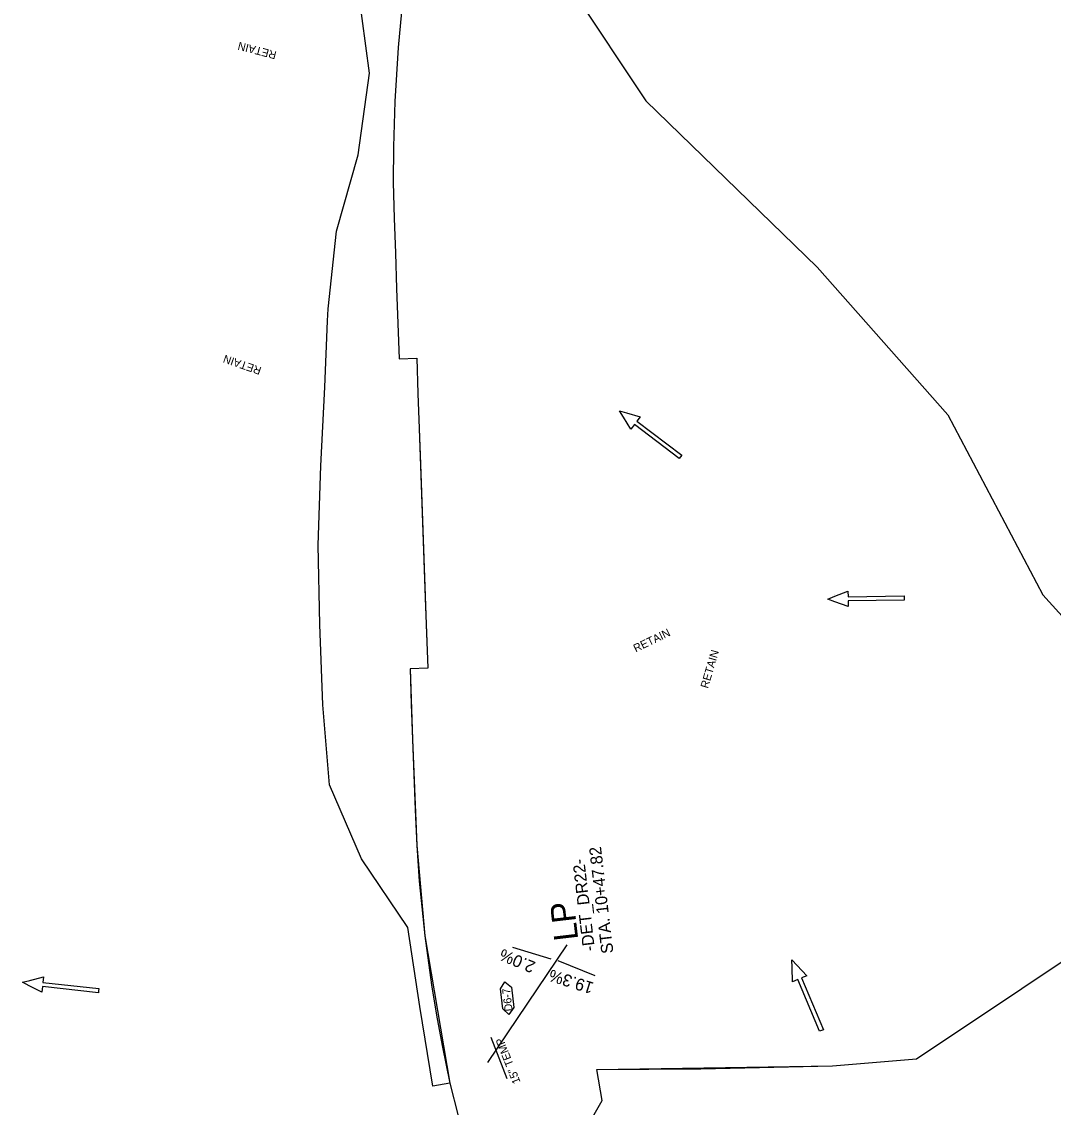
# Model space of a CAD drawing. Extents: x 465700 to 483515, y 488970 to 507540.
# Drawn here: x 474370 to 475014, y 503745 to 504423 of the extents above; entities that cross this region are included whole.
import ezdxf

# ---------------------------------------------------------------- set-up
doc = ezdxf.new("R2010")
doc.units = 0
for name, color, linetype in [('Default', 7, 'Continuous'), ('Exist Plan Preparation Drainage Flow Arrows', 7, 'Continuous'), ('Exist Plan Preparation Watershed Blue', 7, 'Continuous'), ('Prop Drainage Structure Box Number Symbol CELL', 7, 'Continuous'), ('Prop Drainage Structure Pipe Collar Label', 7, 'Continuous'), ('Prop Drainage Structure Pipe Side Drain 15in', 7, 'Continuous'), ('Prop Drainage Structure Pipe Side Drain 15in Label', 7, 'Continuous'), ('Prop Plan Preparation Sag', 7, 'Continuous'), ('Prop Plan Preparation Sag Label', 7, 'Continuous'), ('Scratch_Level_4', 7, 'Continuous')]:
    doc.layers.add(name, color=color, linetype=linetype)

# ---------------------------------------------------------------- blocks, each defined once
blk = doc.blocks.new('Existing ground flow arrow')
at = {"layer": 'Default'}
blk.add_line((2.5, -4.33), (2.5, -4.33), dxfattribs=at)
blk.add_lwpolyline([(-1.29, -47.2), (-1.28, -12.53), (-4.77, -12.53), (-1.65, -4.33), (0, 0), (1.65, -4.33), (4.78, -12.53), (1.28, -12.52), (1.29, -47.19), (0, -47.2)], close=True, dxfattribs=at)

msp = doc.modelspace()

# ---------------------------------------------------------------- linework, layer by layer
at = {"layer": 'Exist Plan Preparation Watershed Blue'}
for points in [[(474607.44, 504429.48), (474605.35, 504407.31), (474603.28, 504373.45), (474602.39, 504345.32), (474602.36, 504323.05), (474602.88, 504300.79), (474603.66, 504278.8), (474604.43, 504256.82), (474605.21, 504234.83), (474605.99, 504212.84), (474616.98, 504213.23), (474617.76, 504191.25), (474618.53, 504169.26), (474622.27, 504063.56), (474623.82, 504019.58), (474612.83, 504019.19), (474614.39, 503975.22), (474616.99, 503909.02), (474621.99, 503852.61), (474637.56, 503760.43), (474653.18, 503699.27)], [(475043.75, 503145.56), (474975.08, 503218.25), (474906.45, 503290.98), (474841.06, 503366.61), (474822.12, 503390.62), (474781.05, 503446.58), (474765.36, 503472.89), (474733.7, 503528.17), (474717.65, 503560.73), (474707.52, 503583.69), (474695.73, 503610.42), (474686.31, 503634.82), (474679.54, 503653.13), (474672.31, 503674.23), (474692.89, 503679.94), (474732.67, 503749.62), (474729.4, 503768.98), (474794.46, 503769.47), (474876.64, 503771.38), (474928.93, 503775.76), (475126.97, 503907.83)], [(474692.89, 503679.94), (474732.67, 503749.62), (474729.4, 503768.98), (474876.64, 503771.38), (474928.93, 503775.76), (475126.97, 503907.83)]]:
    msp.add_lwpolyline(points, dxfattribs=at)
at = {"layer": 'Prop Drainage Structure Box Number Symbol CELL'}
msp.add_lwpolyline([(474670.8, 503806.93), (474669.36, 503819.45), (474672.1, 503823.9), (474676.11, 503820.38), (474677.55, 503807.86), (474674.45, 503803.48), (474670.8, 503806.93)], dxfattribs=at)
at = {"layer": 'Prop Drainage Structure Pipe Side Drain 15in'}
msp.add_line((474673.45, 503763.18), (474663.56, 503788.99), dxfattribs=at)
at = {"layer": 'Prop Plan Preparation Sag'}
msp.add_line((474661.47, 503773.47), (474710.85, 503846.85), dxfattribs=at)
at = {"layer": 'Prop Plan Preparation Sag Label'}
for p, q in [((474700.83, 503837.92), (474676.93, 503845.25)), ((474705.03, 503837.08), (474728.25, 503827.81))]:
    msp.add_line(p, q, dxfattribs=at)
at = {"layer": 'Scratch_Level_4'}
msp.add_lwpolyline([(475270.85, 503809.14), (475219.84, 504084.06), (475137.95, 504274.18), (475078.19, 504412.9), (474954.65, 504479.02), (474778.74, 504535.52), (474670.15, 504603.36), (474666.14, 504603.36), (474675.38, 504549.78), (474701.44, 504496.46), (474714.87, 504441.96), (474760.12, 504373.88), (474867.06, 504270.09), (474948.55, 504177.85), (475007.9, 504065.5), (475074.01, 503992.37), (475126.97, 503907.83)], close=True, dxfattribs=at)
msp.add_lwpolyline([(474607.44, 504429.48), (474605.35, 504407.31), (474603.28, 504373.45), (474602.39, 504345.32), (474602.36, 504323.05), (474602.88, 504300.78), (474603.66, 504278.8), (474604.43, 504256.82), (474605.21, 504234.83), (474605.99, 504212.84), (474616.98, 504213.23), (474617.76, 504191.25), (474618.53, 504169.26), (474619.32, 504146.98), (474622.85, 504047.05), (474623.82, 504019.58), (474612.83, 504019.19), (474613.61, 503997.21), (474614.39, 503975.22), (474615.16, 503953.24), (474615.94, 503931.25), (474616.99, 503909.02), (474618.59, 503886.73), (474621.99, 503852.61), (474626.27, 503821.92), (474629.25, 503803.06), (474632.77, 503784.03), (474637.56, 503760.43), (474627, 503758.68), (474618.87, 503808.38), (474611.39, 503857.66), (474582.45, 503900.64), (474562.43, 503946.88), (474558.32, 503996.88), (474556.49, 504046.86), (474555.48, 504096.51), (474557.11, 504146.05), (474559.66, 504195.21), (474561.31, 504236.49), (474561.67, 504243.99), (474566.88, 504292.53), (474580.44, 504340.34), (474587.52, 504391.14), (474580.59, 504442.75)], dxfattribs=at)

# ---------------------------------------------------------------- block references
at = {"layer": 'Exist Plan Preparation Drainage Flow Arrows'}
for p, xscale, yscale, rotation in [((474743.53, 504180.48), 1.0124070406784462, 1.0124070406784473, 52.927541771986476), ((474873.61, 504062.82), 1.0124070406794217, 1.012407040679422, 90.77529384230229), ((474851.19, 503837.45), 1.0124070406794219, 1.0124070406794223, 22.853758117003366), ((474370.89, 503823.55), 1.0124070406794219, 1.0124070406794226, 83.62540825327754)]:
    msp.add_blockref('Existing ground flow arrow', p, dxfattribs=dict(at, xscale=xscale, yscale=yscale, rotation=rotation))

# ---------------------------------------------------------------- texts
at = {"layer": 'Prop Drainage Structure Box Number Symbol CELL'}
msp.add_text('D6-7', height=5, rotation=96.55096, dxfattribs=at).set_placement((474676.88, 503805.64))
at = {"layer": 'Prop Drainage Structure Pipe Collar Label'}
for rotation, p in [(165.5043, (474529.82, 504404.71)), (160.86771, (474520.43, 504207.48)), (25.8655, (474753.75, 504029.46)), (73.66734, (474798.83, 504006.71))]:
    msp.add_text('RETAIN', height=5, rotation=rotation, dxfattribs=at).set_placement(p)
at = {"layer": 'Prop Drainage Structure Pipe Side Drain 15in Label'}
msp.add_text('15" TEMP', height=5, rotation=111.57061, dxfattribs=at).set_placement((474681.87, 503761.27))
at = {"layer": 'Prop Plan Preparation Sag Label'}
for s, height, rotation, p in [('STA. 10+47.82', 7.5, 96.69266, (474739.83, 503841.88)), (' -DET_DR22- ', 7.5, 96.69266, (474728.66, 503840.57)), ('LP', 15, 96.69601, (474717.86, 503850.33)), ('2.0%', 7.5, 157.47829, (474691.7, 503835.93)), ('19.3%', 7.5, 162.39462, (474728.06, 503823.14))]:
    msp.add_text(s, height=height, rotation=rotation, dxfattribs=at).set_placement(p)

doc.saveas('drawing.dxf')
